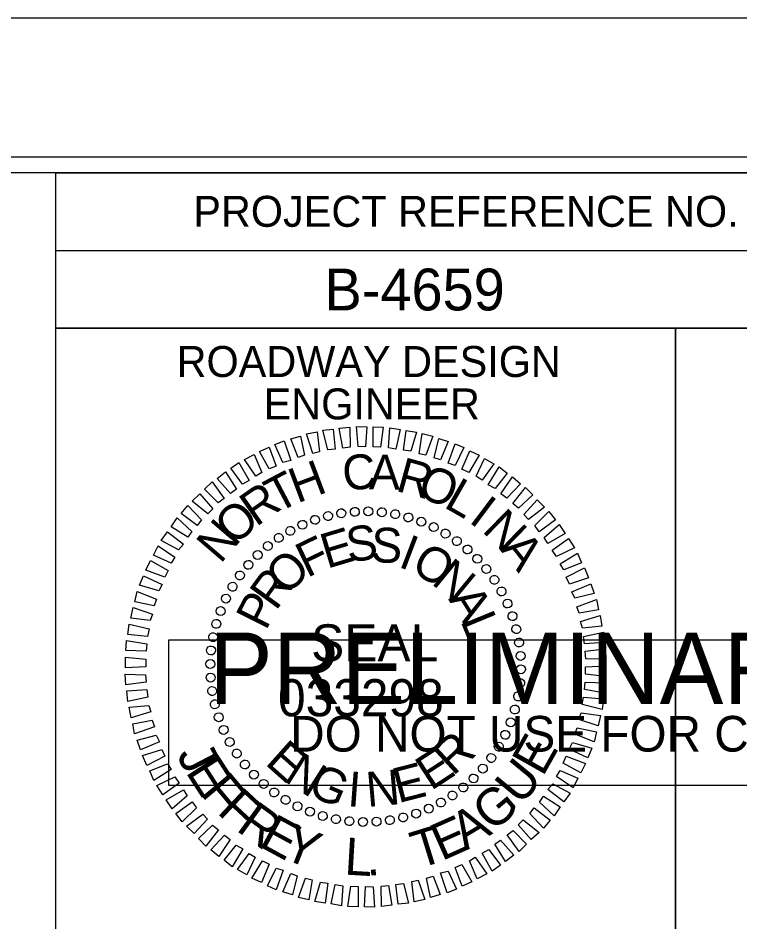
# Model space of a CAD drawing. Extents: x 573786 to 574032, y -53324 to -53148.
# Drawn here: x 573991.09 to 574002.74, y -53229.04 to -53214.45 of the extents above; entities that cross this region are included whole.
import ezdxf

# ---------------------------------------------------------------- set-up
doc = ezdxf.new("R2010")
doc.units = 0
for name, color, linetype in [('Sheet Cutting Line CELL', 7, 'Continuous'), ('Sheet Data Field CELL', 7, 'Continuous'), ('Sheet Plot Border Inside CELL', 7, 'Continuous'), ('Sheet Plot Border Outside CELL', 7, 'Continuous'), ('Sheet Professional Seal CELL', 7, 'Continuous'), ('Sheet Sticker Preliminary CELL', 7, 'Continuous'), ('Sheet Typical CELL', 7, 'Continuous')]:
    doc.layers.add(name, color=color, linetype=linetype)

msp = doc.modelspace()

# ---------------------------------------------------------------- linework, layer by layer
at = {"layer": 'Sheet Cutting Line CELL'}
msp.add_line((574013.401, -53214.447), (573845.001, -53214.447), dxfattribs=at)
at = {"layer": 'Sheet Plot Border Inside CELL'}
msp.add_lwpolyline([(574012.951, -53216.692), (573846.301, -53216.692), (573846.301, -53322.202), (574012.951, -53322.202)], close=True, dxfattribs=at)
at = {"layer": 'Sheet Plot Border Outside CELL'}
msp.add_lwpolyline([(574013.401, -53214.447), (573845.001, -53214.447), (573845.001, -53324.447), (574013.401, -53324.447)], close=True, dxfattribs=at)
at = {"layer": 'Sheet Professional Seal CELL'}
for p, q in [((573995.878, -53222.546), (573995.878, -53222.546)), ((573996.088, -53222.486), (573996.088, -53222.486)), ((573996.308, -53222.446), (573996.308, -53222.446)), ((573996.523, -53222.416), (573996.523, -53222.416)), ((573996.743, -53222.411), (573996.743, -53222.411)), ((573996.963, -53222.426), (573996.963, -53222.426)), ((573997.178, -53222.461), (573997.178, -53222.461)), ((573997.388, -53222.506), (573997.388, -53222.506)), ((573995.678, -53222.626), (573995.678, -53222.626)), ((573997.598, -53222.576), (573997.598, -53222.576)), ((573997.798, -53222.666), (573997.798, -53222.666)), ((573995.293, -53222.841), (573995.293, -53222.841)), ((573995.483, -53222.726), (573995.483, -53222.726)), ((573997.993, -53222.766), (573997.993, -53222.766)), ((573995.118, -53222.966), (573995.118, -53222.966)), ((573998.173, -53222.891), (573998.173, -53222.891)), ((573994.953, -53223.116), (573994.953, -53223.116)), ((573998.348, -53223.026), (573998.348, -53223.026)), ((573994.803, -53223.271), (573994.803, -53223.271)), ((573998.503, -53223.176), (573998.503, -53223.176)), ((573998.653, -53223.341), (573998.653, -53223.341)), ((573994.668, -53223.446), (573994.668, -53223.446)), ((573998.778, -53223.516), (573998.778, -53223.516)), ((573994.543, -53223.626), (573994.543, -53223.626)), ((573998.893, -53223.706), (573998.893, -53223.706)), ((573994.443, -53223.821), (573994.443, -53223.821)), ((573998.993, -53223.901), (573998.993, -53223.901)), ((573994.353, -53224.021), (573994.353, -53224.021)), ((573999.073, -53224.101), (573999.073, -53224.101)), ((573994.283, -53224.231), (573994.283, -53224.231)), ((573994.238, -53224.441), (573994.238, -53224.441)), ((573999.133, -53224.311), (573999.133, -53224.311)), ((573999.173, -53224.531), (573999.173, -53224.531)), ((573994.203, -53224.656), (573994.203, -53224.656)), ((573994.188, -53224.876), (573994.188, -53224.876)), ((573999.203, -53224.746), (573999.203, -53224.746)), ((573996.698, -53224.921), (573996.698, -53224.921)), ((573999.208, -53224.966), (573999.208, -53224.966)), ((573994.193, -53225.096), (573994.193, -53225.096)), ((573994.223, -53225.311), (573994.223, -53225.311)), ((573999.193, -53225.186), (573999.193, -53225.186)), ((573999.158, -53225.401), (573999.158, -53225.401)), ((573994.263, -53225.531), (573994.263, -53225.531)), ((573999.113, -53225.611), (573999.113, -53225.611)), ((573994.323, -53225.741), (573994.323, -53225.741)), ((573999.043, -53225.821), (573999.043, -53225.821)), ((573994.403, -53225.941), (573994.403, -53225.941)), ((573998.953, -53226.021), (573998.953, -53226.021)), ((573994.503, -53226.136), (573994.503, -53226.136)), ((573994.618, -53226.326), (573994.618, -53226.326)), ((573998.853, -53226.216), (573998.853, -53226.216)), ((573998.728, -53226.396), (573998.728, -53226.396)), ((573994.743, -53226.501), (573994.743, -53226.501)), ((573998.593, -53226.571), (573998.593, -53226.571)), ((573994.893, -53226.666), (573994.893, -53226.666)), ((573998.443, -53226.726), (573998.443, -53226.726)), ((573995.048, -53226.816), (573995.048, -53226.816)), ((573998.278, -53226.876), (573998.278, -53226.876)), ((573995.223, -53226.951), (573995.223, -53226.951)), ((573995.403, -53227.076), (573995.403, -53227.076)), ((573998.103, -53227.001), (573998.103, -53227.001)), ((573995.598, -53227.176), (573995.598, -53227.176)), ((573997.718, -53227.216), (573997.718, -53227.216)), ((573997.913, -53227.116), (573997.913, -53227.116)), ((573995.798, -53227.266), (573995.798, -53227.266)), ((573996.008, -53227.336), (573996.008, -53227.336)), ((573997.308, -53227.356), (573997.308, -53227.356)), ((573997.518, -53227.296), (573997.518, -53227.296)), ((573996.218, -53227.381), (573996.218, -53227.381)), ((573996.433, -53227.416), (573996.433, -53227.416)), ((573996.653, -53227.431), (573996.653, -53227.431)), ((573996.873, -53227.426), (573996.873, -53227.426)), ((573997.088, -53227.396), (573997.088, -53227.396))]:
    msp.add_line(p, q, dxfattribs=at)
for points in [[(573996.088, -53221.421), (573996.008, -53221.101), (573996.173, -53221.086), (573996.208, -53221.406)], [(573996.328, -53221.391), (573996.273, -53221.071), (573996.443, -53221.051), (573996.448, -53221.376)], [(573996.578, -53221.366), (573996.553, -53221.041), (573996.718, -53221.046), (573996.698, -53221.371)], [(573996.818, -53221.371), (573996.818, -53221.046), (573996.983, -53221.051), (573996.938, -53221.376)], [(573997.068, -53221.386), (573997.088, -53221.061), (573997.253, -53221.091), (573997.188, -53221.406)], [(573995.608, -53221.541), (573995.493, -53221.241), (573995.648, -53221.196), (573995.713, -53221.506)], [(573995.848, -53221.476), (573995.743, -53221.161), (573995.913, -53221.126), (573995.953, -53221.451)], [(573997.308, -53221.426), (573997.353, -53221.106), (573997.518, -53221.131), (573997.428, -53221.441)], [(573997.563, -53221.481), (573997.613, -53221.156), (573997.783, -53221.196), (573997.668, -53221.506)], [(573997.803, -53221.546), (573997.878, -53221.236), (573998.033, -53221.286), (573997.908, -53221.581)], [(573995.143, -53221.726), (573994.983, -53221.446), (573995.138, -53221.376), (573995.253, -53221.681)], [(573995.363, -53221.621), (573995.233, -53221.331), (573995.383, -53221.271), (573995.488, -53221.591)], [(573998.028, -53221.636), (573998.143, -53221.321), (573998.283, -53221.381), (573998.143, -53221.671)], [(573994.928, -53221.846), (573994.743, -53221.576), (573994.898, -53221.496), (573995.023, -53221.786)], [(573998.253, -53221.731), (573998.378, -53221.436), (573998.533, -53221.506), (573998.363, -53221.786)], [(573994.708, -53221.971), (573994.523, -53221.716), (573994.653, -53221.621), (573994.818, -53221.911)], [(573998.483, -53221.846), (573998.618, -53221.561), (573998.768, -53221.646), (573998.578, -53221.906)], [(573994.518, -53222.121), (573994.303, -53221.881), (573994.438, -53221.776), (573994.613, -53222.056)], [(573998.678, -53221.981), (573998.853, -53221.691), (573998.983, -53221.796), (573998.788, -53222.041)], [(573994.318, -53222.276), (573994.098, -53222.056), (573994.218, -53221.936), (573994.413, -53222.206)], [(573998.883, -53222.131), (573999.068, -53221.856), (573999.198, -53221.966), (573998.978, -53222.201)], [(573999.073, -53222.286), (573999.278, -53222.026), (573999.398, -53222.146), (573999.168, -53222.361)], [(573994.153, -53222.451), (573993.898, -53222.246), (573994.023, -53222.131), (573994.233, -53222.371)], [(573999.253, -53222.461), (573999.468, -53222.226), (573999.588, -53222.346), (573999.328, -53222.541)], [(573993.978, -53222.641), (573993.718, -53222.446), (573993.828, -53222.316), (573994.048, -53222.551)], [(573993.828, -53222.831), (573993.558, -53222.661), (573993.653, -53222.516), (573993.893, -53222.736)], [(573999.428, -53222.641), (573999.658, -53222.416), (573999.763, -53222.551), (573999.498, -53222.741)], [(573999.578, -53222.836), (573999.823, -53222.626), (573999.918, -53222.771), (573999.638, -53222.931)], [(573993.678, -53223.031), (573993.398, -53222.881), (573993.498, -53222.741), (573993.758, -53222.941)], [(573993.558, -53223.246), (573993.273, -53223.121), (573993.348, -53222.966), (573993.618, -53223.151)], [(573999.708, -53223.041), (573999.973, -53222.851), (574000.068, -53223.001), (573999.778, -53223.141)], [(573999.838, -53223.261), (574000.118, -53223.086), (574000.183, -53223.241), (573999.898, -53223.356)], [(573993.458, -53223.476), (573993.148, -53223.361), (573993.223, -53223.206), (573993.508, -53223.366)], [(573999.938, -53223.476), (574000.233, -53223.326), (574000.298, -53223.486), (573999.988, -53223.586)], [(573993.358, -53223.696), (573993.048, -53223.606), (573993.113, -53223.451), (573993.413, -53223.591)], [(573993.283, -53223.936), (573992.973, -53223.871), (573993.008, -53223.706), (573993.323, -53223.831)], [(574000.028, -53223.711), (574000.333, -53223.581), (574000.388, -53223.736), (574000.078, -53223.816)], [(574000.108, -53223.951), (574000.428, -53223.836), (574000.458, -53224.001), (574000.143, -53224.056)], [(573993.218, -53224.176), (573992.908, -53224.136), (573992.943, -53223.966), (573993.258, -53224.071)], [(574000.168, -53224.191), (574000.483, -53224.096), (574000.513, -53224.266), (574000.198, -53224.296)], [(573993.178, -53224.431), (573992.858, -53224.401), (573992.878, -53224.231), (573993.203, -53224.311)], [(574000.213, -53224.431), (574000.538, -53224.361), (574000.553, -53224.531), (574000.233, -53224.551)], [(573993.153, -53224.671), (573992.828, -53224.661), (573992.838, -53224.496), (573993.163, -53224.551)], [(574000.243, -53224.671), (574000.568, -53224.631), (574000.578, -53224.801), (574000.253, -53224.791)], [(573993.148, -53224.921), (573992.823, -53224.936), (573992.823, -53224.766), (573993.148, -53224.801)], [(574000.248, -53224.921), (574000.573, -53224.906), (574000.573, -53225.076), (574000.248, -53225.041)], [(573993.153, -53225.171), (573992.828, -53225.211), (573992.818, -53225.041), (573993.143, -53225.051)], [(574000.243, -53225.171), (574000.568, -53225.181), (574000.558, -53225.346), (574000.233, -53225.291)], [(573993.183, -53225.411), (573992.858, -53225.481), (573992.843, -53225.311), (573993.163, -53225.291)], [(574000.218, -53225.411), (574000.538, -53225.441), (574000.518, -53225.611), (574000.193, -53225.531)], [(573993.228, -53225.651), (573992.913, -53225.746), (573992.883, -53225.576), (573993.198, -53225.546)], [(574000.178, -53225.666), (574000.488, -53225.706), (574000.453, -53225.876), (574000.138, -53225.771)], [(573993.288, -53225.891), (573992.968, -53226.006), (573992.938, -53225.841), (573993.253, -53225.786)], [(574000.113, -53225.906), (574000.423, -53225.971), (574000.388, -53226.136), (574000.073, -53226.011)], [(573993.368, -53226.131), (573993.063, -53226.261), (573993.008, -53226.106), (573993.318, -53226.026)], [(574000.038, -53226.146), (574000.348, -53226.236), (574000.283, -53226.391), (573999.983, -53226.251)], [(573993.458, -53226.366), (573993.163, -53226.516), (573993.098, -53226.356), (573993.408, -53226.256)], [(573993.558, -53226.581), (573993.278, -53226.756), (573993.213, -53226.601), (573993.498, -53226.486)], [(573999.938, -53226.366), (574000.248, -53226.481), (574000.173, -53226.636), (573999.888, -53226.476)], [(573999.838, -53226.596), (574000.123, -53226.721), (574000.048, -53226.876), (573999.778, -53226.691)], [(573993.688, -53226.801), (573993.423, -53226.991), (573993.328, -53226.841), (573993.618, -53226.701)], [(573993.818, -53227.006), (573993.573, -53227.216), (573993.478, -53227.071), (573993.758, -53226.911)], [(573999.718, -53226.811), (573999.998, -53226.961), (573999.898, -53227.101), (573999.638, -53226.901)], [(573999.568, -53227.011), (573999.838, -53227.181), (573999.743, -53227.326), (573999.503, -53227.106)], [(573993.968, -53227.201), (573993.738, -53227.426), (573993.633, -53227.291), (573993.898, -53227.101)], [(573999.418, -53227.201), (573999.678, -53227.396), (573999.568, -53227.526), (573999.348, -53227.291)], [(573994.143, -53227.381), (573993.928, -53227.616), (573993.808, -53227.496), (573994.068, -53227.301)], [(573994.323, -53227.556), (573994.118, -53227.816), (573993.998, -53227.696), (573994.228, -53227.481)], [(573999.243, -53227.391), (573999.498, -53227.596), (573999.373, -53227.711), (573999.163, -53227.471)], [(573994.513, -53227.711), (573994.328, -53227.986), (573994.198, -53227.876), (573994.418, -53227.641)], [(573999.078, -53227.566), (573999.298, -53227.786), (573999.178, -53227.906), (573998.983, -53227.636)], [(573994.718, -53227.861), (573994.543, -53228.151), (573994.413, -53228.046), (573994.608, -53227.801)], [(573998.878, -53227.721), (573999.093, -53227.961), (573998.958, -53228.066), (573998.783, -53227.786)], [(573994.913, -53227.996), (573994.778, -53228.281), (573994.628, -53228.196), (573994.818, -53227.936)], [(573998.688, -53227.871), (573998.873, -53228.126), (573998.743, -53228.221), (573998.578, -53227.931)], [(573995.143, -53228.111), (573995.018, -53228.406), (573994.863, -53228.336), (573995.033, -53228.056)], [(573998.468, -53227.996), (573998.653, -53228.266), (573998.498, -53228.346), (573998.373, -53228.056)], [(573995.368, -53228.206), (573995.253, -53228.521), (573995.113, -53228.461), (573995.253, -53228.171)], [(573998.033, -53228.221), (573998.163, -53228.511), (573998.013, -53228.571), (573997.908, -53228.251)], [(573998.253, -53228.116), (573998.413, -53228.396), (573998.258, -53228.466), (573998.143, -53228.161)], [(573995.593, -53228.296), (573995.518, -53228.606), (573995.363, -53228.556), (573995.488, -53228.261)], [(573995.833, -53228.361), (573995.783, -53228.686), (573995.613, -53228.646), (573995.728, -53228.336)], [(573997.548, -53228.366), (573997.653, -53228.681), (573997.483, -53228.716), (573997.443, -53228.391)], [(573997.788, -53228.301), (573997.903, -53228.601), (573997.748, -53228.646), (573997.683, -53228.336)], [(573996.088, -53228.416), (573996.043, -53228.736), (573995.878, -53228.711), (573995.968, -53228.401)], [(573996.328, -53228.456), (573996.308, -53228.781), (573996.143, -53228.751), (573996.208, -53228.436)], [(573996.578, -53228.471), (573996.578, -53228.796), (573996.413, -53228.791), (573996.458, -53228.466)], [(573996.818, -53228.476), (573996.843, -53228.801), (573996.678, -53228.796), (573996.698, -53228.471)], [(573997.068, -53228.451), (573997.123, -53228.771), (573996.953, -53228.791), (573996.948, -53228.466)], [(573997.308, -53228.421), (573997.388, -53228.741), (573997.223, -53228.756), (573997.188, -53228.436)]]:
    msp.add_lwpolyline(points, close=True, dxfattribs=at)
for centre, major_axis in [((573996.305, -53222.443), (-0.0113, 0.0711)), ((573996.523, -53222.419), (-0.005, 0.0718)), ((573996.741, -53222.413), (0.0013, 0.072)), ((573996.96, -53222.426), (0.0075, 0.0716)), ((573997.176, -53222.459), (0.0137, 0.0707)), ((573995.678, -53222.629), (-0.0293, 0.0658)), ((573995.881, -53222.549), (-0.0234, 0.0681)), ((573996.091, -53222.487), (-0.0174, 0.0699)), ((573997.389, -53222.51), (0.0198, 0.0692)), ((573997.596, -53222.579), (0.0258, 0.0672)), ((573995.482, -53222.727), (-0.0349, 0.063)), ((573997.797, -53222.666), (0.0316, 0.0647)), ((573997.989, -53222.771), (0.0371, 0.0617)), ((573995.295, -53222.841), (-0.0403, 0.0597)), ((573998.172, -53222.892), (0.0423, 0.0582)), ((573995.119, -53222.971), (-0.0453, 0.056)), ((573998.343, -53223.028), (0.0472, 0.0543)), ((573994.955, -53223.116), (-0.05, 0.0518)), ((573998.502, -53223.178), (0.0518, 0.05)), ((573994.805, -53223.275), (-0.0543, 0.0472)), ((573998.647, -53223.342), (0.056, 0.0453)), ((573994.669, -53223.446), (-0.0582, 0.0423)), ((573994.548, -53223.629), (-0.0617, 0.0371)), ((573998.777, -53223.518), (0.0597, 0.0403)), ((573998.891, -53223.705), (0.063, 0.0349)), ((573994.443, -53223.821), (-0.0647, 0.0316)), ((573998.989, -53223.9), (0.0658, 0.0293)), ((573994.356, -53224.022), (-0.0672, 0.0258)), ((573994.287, -53224.229), (-0.0692, 0.0198)), ((573999.069, -53224.104), (0.0681, 0.0234)), ((573999.131, -53224.314), (0.0699, 0.0174)), ((573994.236, -53224.442), (-0.0707, 0.0137)), ((573994.203, -53224.658), (-0.0716, 0.0075)), ((573999.175, -53224.528), (0.0711, 0.0113)), ((573999.2, -53224.746), (0.0718, 0.005)), ((573994.19, -53224.877), (-0.072, 0.0013)), ((573994.196, -53225.096), (-0.0718, -0.005)), ((573999.205, -53224.964), (0.072, -0.0013)), ((573999.192, -53225.183), (0.0716, -0.0075)), ((573994.221, -53225.313), (-0.0711, -0.0113)), ((573999.16, -53225.399), (0.0707, -0.0137)), ((573994.264, -53225.527), (-0.0699, -0.0174)), ((573999.108, -53225.612), (0.0692, -0.0198)), ((573994.326, -53225.737), (-0.0681, -0.0234)), ((573999.039, -53225.819), (0.0672, -0.0258)), ((573994.406, -53225.941), (-0.0658, -0.0293)), ((573994.504, -53226.136), (-0.063, -0.0349)), ((573998.952, -53226.02), (0.0647, -0.0316)), ((573998.847, -53226.212), (0.0617, -0.0371)), ((573994.618, -53226.323), (-0.0597, -0.0403)), ((573998.727, -53226.395), (0.0582, -0.0423)), ((573994.749, -53226.499), (-0.056, -0.0453)), ((573998.59, -53226.566), (0.0543, -0.0472)), ((573994.894, -53226.663), (-0.0518, -0.05)), ((573995.052, -53226.813), (-0.0472, -0.0543)), ((573998.44, -53226.725), (0.05, -0.0518)), ((573995.223, -53226.95), (-0.0423, -0.0582)), ((573998.1, -53227), (0.0403, -0.0597)), ((573998.276, -53226.87), (0.0453, -0.056)), ((573995.406, -53227.07), (-0.0371, -0.0617)), ((573997.914, -53227.114), (0.0349, -0.063)), ((573995.598, -53227.175), (-0.0316, -0.0647)), ((573995.799, -53227.262), (-0.0258, -0.0672)), ((573997.514, -53227.292), (0.0234, -0.0681)), ((573997.718, -53227.212), (0.0293, -0.0658)), ((573996.006, -53227.331), (-0.0198, -0.0692)), ((573996.219, -53227.382), (-0.0137, -0.0707)), ((573996.435, -53227.415), (-0.0075, -0.0716)), ((573996.654, -53227.428), (-0.0013, -0.072)), ((573996.873, -53227.422), (0.005, -0.0718)), ((573997.09, -53227.398), (0.0113, -0.0711)), ((573997.304, -53227.354), (0.0174, -0.0699))]:
    msp.add_ellipse(centre, major_axis=major_axis, ratio=0.999708, dxfattribs=at)
at = {"layer": 'Sheet Sticker Preliminary CELL'}
msp.add_lwpolyline([(573993.52, -53226.836), (573993.52, -53224.486), (574008.22, -53224.486), (574008.22, -53226.836)], close=True, dxfattribs=at)
at = {"layer": 'Sheet Typical CELL'}
for p, q in [((573991.696, -53218.202), (574011.701, -53218.202)), ((574001.701, -53219.452), (574001.701, -53230.697))]:
    msp.add_line(p, q, dxfattribs=at)
for points in [[(574011.701, -53216.947), (573861.701, -53216.947), (573861.701, -53321.947), (574011.701, -53321.947)], [(573991.696, -53216.947), (574011.701, -53216.947), (574011.701, -53219.452), (573991.696, -53219.452)], [(573991.696, -53219.452), (574001.701, -53219.452), (574001.701, -53230.702), (573991.696, -53230.702)], [(574001.701, -53219.452), (574011.701, -53219.452), (574011.701, -53230.702), (574001.701, -53230.702)]]:
    msp.add_lwpolyline(points, close=True, dxfattribs=at)

# ---------------------------------------------------------------- texts
at = {"layer": 'Sheet Data Field CELL'}
msp.add_text('B-4659', height=0.675, dxfattribs=at).set_placement((573996.034, -53219.167))
at = {"layer": 'Sheet Professional Seal CELL'}
for s, height, rotation, p in [('C', 0.564, 6.2199, (573996.353, -53222.086)), ('A', 0.564, 359.0203, (573996.748, -53222.056)), ('H', 0.564, 20.6195, (573995.593, -53222.286)), ('R', 0.564, 344.6211, (573997.168, -53222.076)), ('T', 0.564, 27.8198, (573995.268, -53222.451)), ('O', 0.564, 337.4212, (573997.503, -53222.151)), ('L', 0.564, 330.2209, (573997.943, -53222.336)), ('R', 0.564, 35.0205, (573994.928, -53222.671)), ('I', 0.564, 323.0201, (573998.348, -53222.576)), ('O', 0.564, 42.2217, (573994.583, -53222.981)), ('N', 0.564, 315.8189, (573998.563, -53222.731)), ('N', 0.564, 49.4235, (573994.353, -53223.271)), ('E', 0.564, 16.6111, (573996.073, -53223.341)), ('S', 0.564, 7.2556, (573996.418, -53223.236)), ('S', 0.564, 357.9004, (573996.778, -53223.231)), ('F', 0.564, 25.967, (573995.753, -53223.491)), ('I', 0.564, 339.1896, (573997.208, -53223.301)), ('A', 0.564, 308.6172, (573998.858, -53223.026)), ('O', 0.564, 329.8335, (573997.408, -53223.371)), ('O', 0.564, 44.6812, (573995.423, -53223.786)), ('N', 0.564, 320.4766, (573997.743, -53223.571)), ('R', 0.564, 54.0397, (573995.248, -53224.031)), ('A', 0.564, 301.7603, (573998.028, -53223.831)), ('P', 0.564, 63.3989, (573995.088, -53224.351)), ('L', 0.564, 292.4008, (573998.223, -53224.176)), ('SEAL', 0.5998, 360, (573995.818, -53224.836)), ('R', 0.564, 42.4814, (573998.108, -53226.696)), ('E', 0.6, 60.587, (573999.557, -53226.71)), ('E', 0.564, 318.2769, (573995.058, -53226.486)), ('J', 0.6, 297.5615, (573993.638, -53226.343)), ('N', 0.564, 327.634, (573995.358, -53226.756)), ('E', 0.564, 33.1241, (573997.753, -53226.931)), ('E', 0.6, 302.8193, (573993.782, -53226.617)), ('E', 0.564, 14.4118, (573997.223, -53227.126)), ('U', 0.6, 50.6494, (573999.206, -53227.177)), ('F', 0.6, 309.9286, (573994.014, -53226.965)), ('G', 0.564, 336.9902, (573995.738, -53226.981)), ('I', 0.564, 355.7012, (573996.393, -53227.171)), ('N', 0.564, 5.0564, (573996.728, -53227.186)), ('F', 0.6, 316.9452, (573994.284, -53227.277)), ('G', 0.6, 39.9236, (573998.742, -53227.604)), ('R', 0.6, 323.9618, (573994.59, -53227.555)), ('A', 0.6, 31.0833, (573998.305, -53227.887)), ('E', 0.6, 331.4421, (573994.951, -53227.807)), ('E', 0.6, 23.9739, (573997.926, -53228.063)), ('Y', 0.6, 338.5514, (573995.321, -53228.001)), ('T', 0.6, 17.1737, (573997.545, -53228.186)), ('L', 0.6, 356.6648, (573996.347, -53228.276)), ('.', 0.6, 2.9396, (573996.716, -53228.294))]:
    msp.add_text(s, height=height, rotation=rotation, dxfattribs=at).set_placement(p)
msp.add_text('033298', height=0.5998, dxfattribs=at).set_placement((573995.283, -53225.721))
at = {"layer": 'Sheet Sticker Preliminary CELL'}
for s, height, p in [('PRELIMINARY PLANS', 1.152, (573994.17, -53225.521)), ('DO NOT USE FOR CONSTRUCTION', 0.576, (573995.48, -53226.291))]:
    msp.add_text(s, height=height, dxfattribs=at).set_placement(p)
at = {"layer": 'Sheet Typical CELL'}
for s, height, p in [('PROJECT REFERENCE NO.', 0.50001, (573993.916, -53217.817)), ('ROADWAY DESIGN', 0.50001, (573993.646, -53220.242)), ('ENGINEER', 0.5, (573995.051, -53220.927))]:
    msp.add_text(s, height=height, dxfattribs=at).set_placement(p)

doc.saveas('drawing.dxf')
